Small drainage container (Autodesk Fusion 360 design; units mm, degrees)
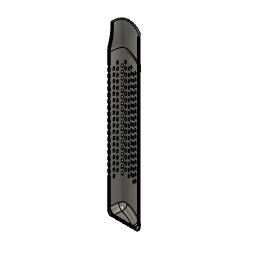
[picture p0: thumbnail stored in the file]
sketch "Schizzo1" plane through (0, 0, 0) normal (0, 1, 0) x axis (1, 0, 0)
  line L1 (0, -20) -> (0, 20)
  line L2 (45.8258, 0) -> (0, 20)
  line L3 (0, -20) -> (45.8258, 0)
  line L4 (45.8258, 0) -> (0, 0)
  curve K1 (0, -17) -> (0, 0)
  curve K2 (6.8983, -16.9893) -> (0, -17)
  curve K3 (43.5589, -0.9893) -> (6.8983, -16.9893)
  curve K4 (43.5589, 0.9893) -> (43.5589, -0.9893)
  curve K5 (6.8983, 16.9893) -> (43.5589, 0.9893)
  curve K6 (0, 17) -> (6.8983, 16.9893)
  curve K7 (0, 0) -> (0, 17)
  curve K8 (0, 0) -> (0, 0)
  line L5 (0, -17) -> (0, 0)
  line L6 (0, 17) -> (0, 0)
  point P6 (0, 0)
  point P4 (0, 0)
  point P7 (0, -17)
  point P8 (6.8983, -16.9893)
  point P9 (43.5589, -0.9893)
  point P10 (43.5589, 0.9893)
  point P11 (6.8983, 16.9893)
  point P14 (0, 0)
  point P15 (0, -17)
  point P12 (0, 17)
  point P16 (0, 17)
  point P2 (0, -20)
  point P3 (0, 20)
  point P5 (45.8258, 0)
  midpoint L1 P6
  vertical L1
  horizontal L4
  coincident P4 P6
  coincident L1 P7
  coincident L3 P8
  coincident L3 P9
  coincident L2 P10
  coincident L2 P11
  coincident P4 P14
  coincident P7 P15
  coincident P12 P16
  perpendicular L4 L6
  vertical K4
  dimension "d2" distance P2 P3 = 40
  dimension "d7" distance P2 P5 = 50
  dimension "d8" distance P6 P16 = 17
  dimension "d9" distance P14 P15 = 17
  dimension "d10" distance P10 P11 = 40
  dimension "d11" distance P8 P9 = 40
  dimension "d18" = -1.5
extrude "Estrusione1" new body sketch "Schizzo1" profile of L4 K8 along normal blind 150
extrude "Estrusione3" add sketch "Schizzo1" profile of L4 along normal blind 1.5
fillet "Raccordo3" radius 5
sketch "Schizzo2" plane through (0, 0, 0) normal (1, 0, 0) x axis (0, 0, -1)
  line L1 (0.75, 138) -> (0.75, 136)
  line L2 (-0.75, 136) -> (-0.75, 138)
  line L3 (0, 138) -> (0, 136)
  line L4 (0, 137) -> (0, 0)
  arc A1 centre (0, 138) radius 0.75 clockwise from (-0.75, 138) to (0.75, 138)
  arc A2 centre (0, 136) radius 0.75 clockwise from (0.75, 136) to (-0.75, 136)
  point P8 (0, 137)
  point P1 (0, 0)
  point P9 (0, 0)
  point P10 (0, 137)
  point P6 (0, 136)
  point P7 (0, 138)
  tangent L1 A1
  tangent A1 L2
  parallel L1 L2
  tangent L2 A2
  tangent L1 A2
  vertical L3
  midpoint L3 P8
  coincident P1 P9
  vertical L4
  coincident P8 P10
  dimension "d23" distance L1 L2 = 1.5
  dimension "d24" distance P6 P7 = 2
  dimension "d59" distance P9 P10 = 137 (= "142.000002116 mm - 5 mm")
extrude "Estrusione4" cut sketch "Schizzo2" profile of L1 A1 L2 A2 to an object
path_pattern "SerieTraiettoria1" PathPatternDelta 34.6978
mirror "Specchio1" mirrorStitchTolerance 0.1
sketch "Schizzo3" plane through (0, 0, 0) normal (1, 0, 0) x axis (0, 0, -1)
  line L1 (-4.25, 134) -> (-4.25, 132)
  line L2 (-5.75, 132) -> (-5.75, 134)
  line L3 (-5, 134) -> (-5, 132)
  line L4 (-5, 0) -> (-5, 133)
  line L5 (0, 0) -> (-5, 0)
  arc A1 centre (-5, 134) radius 0.75 clockwise from (-5.75, 134) to (-4.25, 134)
  arc A2 centre (-5, 132) radius 0.75 clockwise from (-4.25, 132) to (-5.75, 132)
  point P8 (-5, 133)
  point P9 (-5, 133)
  point P1 (0, 0)
  point P11 (0, 0)
  point P6 (-5, 132)
  point P7 (-5, 134)
  point P10 (-5, 0)
  tangent L1 A1
  tangent A1 L2
  parallel L1 L2
  tangent L2 A2
  tangent L1 A2
  vertical L3
  midpoint L3 P8
  coincident P8 P9
  parallel L3 L4
  coincident P1 P11
  perpendicular L4 L5
  dimension "d32" distance L1 L2 = 1.5
  dimension "d33" distance P6 P7 = 2
  dimension "d60" distance P9 P10 = 133 (= "138.0000020564 mm - 5 mm")
extrude "Estrusione5" cut sketch "Schizzo3" profile of L1 A1 L2 A2 along normal blind 2
path_pattern "SerieTraiettoria2" PathPatternDelta 25.1145
mirror "Specchio2" mirrorStitchTolerance 0.1
rectangular_pattern "Serie R" countU 18 uSpaceDistance -100 vSpaceDistance 0
chamfer "Smusso" distance 3 distance 2
sketch "Schizzo4" plane through (0, 150, 0) normal (0, 1, 0) x axis (-1, 0, 0)
  line L1 (0, 0) -> (-42.5, 0)
  point P1 (0, 0)
  point P3 (0, 0)
  coincident P1 P3
  horizontal L1
work_plane "Piano di lavoro1" sketch "Schizzo4" AlongDistance 30
sketch "Schizzo5" plane through (17.7061, 180, 0) normal (0, 1, 0) x axis (1, 0, 0)
  curve K1 (-14.1843, -11.4353) -> (-14.1843, 0)
  curve K2 (-4, -14) -> (-14.1843, -11.4353)
  curve K3 (23.2456, -1.1467) -> (-4, -14)
  curve K4 (23.2456, 1.1467) -> (23.2456, -1.1467)
  curve K5 (-4, 14) -> (23.2456, 1.1467)
  curve K6 (-14.1843, 11.8868) -> (-4, 14)
  curve K7 (-14.1843, 0) -> (-14.1843, 11.8868)
  curve K8 (-14.1843, 0) -> (-14.1843, 0)
  point P8 (-14.1843, 11.8868)
  point P2 (-14.1843, 0)
  point P9 (-14.1843, 0)
  coincident P8
  coincident P2 P9
  parallel K1 K7
sketch "Schizzo6" plane through (0, 0, 0) normal (0, 0, 1) x axis (1, 0, 0)
  curve K1 (0.0014, 160.046) -> (0, 150)
  curve K2 (3.5218, 160.5734) -> (0.0014, 160.046)
  curve K3 (3.5218, 180) -> (3.5218, 160.5734)
  curve K4 (3.5218, 180) -> (0, 150)
  line L1 (13.7061, 180) -> (3.5218, 180)
  line L2 (33.5076, 150) -> (33.4619, 180)
  point P2 (3.5218, 180)
  point P8 (3.5218, 180)
  point P3 (33.4619, 180)
  point P11 (33.4619, 180)
  coincident P2 P8
  perpendicular K3 L1
  coincident P3 P11
work_plane "Piano di lavoro2" AlongDistance 17
sketch "Schizzo7" plane through (17, 0, 0) normal (1, 0, 0) x axis (0, 0, -1)
  curve K1 (-11.9, 160.0016) -> (-11.7395, 150)
  curve K2 (-9.8125, 160.0015) -> (-11.9, 160.0016)
  curve K3 (-10.1921, 180) -> (-9.8125, 160.0015)
  curve K4 (-10.1921, 180) -> (-11.7395, 150)
  curve K5 (11.9001, 160.0043) -> (11.7395, 150)
  curve K6 (9.6921, 160.004) -> (11.9001, 160.0043)
  curve K7 (10.3156, 180) -> (9.6921, 160.004)
  curve K8 (10.3156, 180) -> (11.7395, 150)
  point P4 (-11.7395, 150)
  point P6 (-11.7395, 150)
  point P2 (-10.1921, 180)
  point P9 (-10.1921, 180)
  point P5 (11.7395, 150)
  point P10 (11.7395, 150)
  point P3 (10.3156, 180)
  point P13 (10.3156, 180)
  coincident P4 P6
  coincident P2 P9
  coincident P5 P10
  coincident P3 P13
loft "Loft1"
sketch "Schizzo10" plane through (0, 0, 0) normal (1, 0, 0) x axis (0, 0, -1)
thicken "Ispessisci" Thickness -1.5
sketch "Schizzo9" plane through (0, 150, 0) normal (0, 1, 0) x axis (-1, 0, 0)
  dimension "d52" distance = -0.75 (= "( -1.5 / 2 ) * 1 mm")
  dimension "d53" distance = -0.75
  dimension "d54" distance = -0.8
extrude "Estrusione6" cut sketch "Schizzo9" against normal blind 3
extrude "Estrusione7" add sketch "Schizzo9" against normal blind 3
sketch "Schizzo11" plane through (0, 0, 0) normal (0, 0, 1) x axis (1, 0, 0)
sketch "Schizzo12" plane through (0, 0, 0) normal (0, 0, 1) x axis (1, 0, 0)
work_plane "Piano di lavoro3" AlongDistance 142
work_plane "Piano di lavoro4" AlongDistance 17
split "Dividi1"
split "Dividi2"
split "Dividi3"
sketch "Schizzo8" plane through (0, 150, 0) normal (0, 1, 0) x axis (-1, 0, 0)
  curve K1 (-30.2634, -0.0045) -> (-3.25, 0)
  curve K2 (-3.25, 0) -> (-30.2634, -0.0045)
  dimension "d50" distance = 0.15
  dimension "d51" distance = 1.75
extrude "Estrusione2" new body sketch "Schizzo1" profile of L1 L2 L3 L4 K8 L5 L6 along normal blind 150
fillet "Raccordo2" radius 5 5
